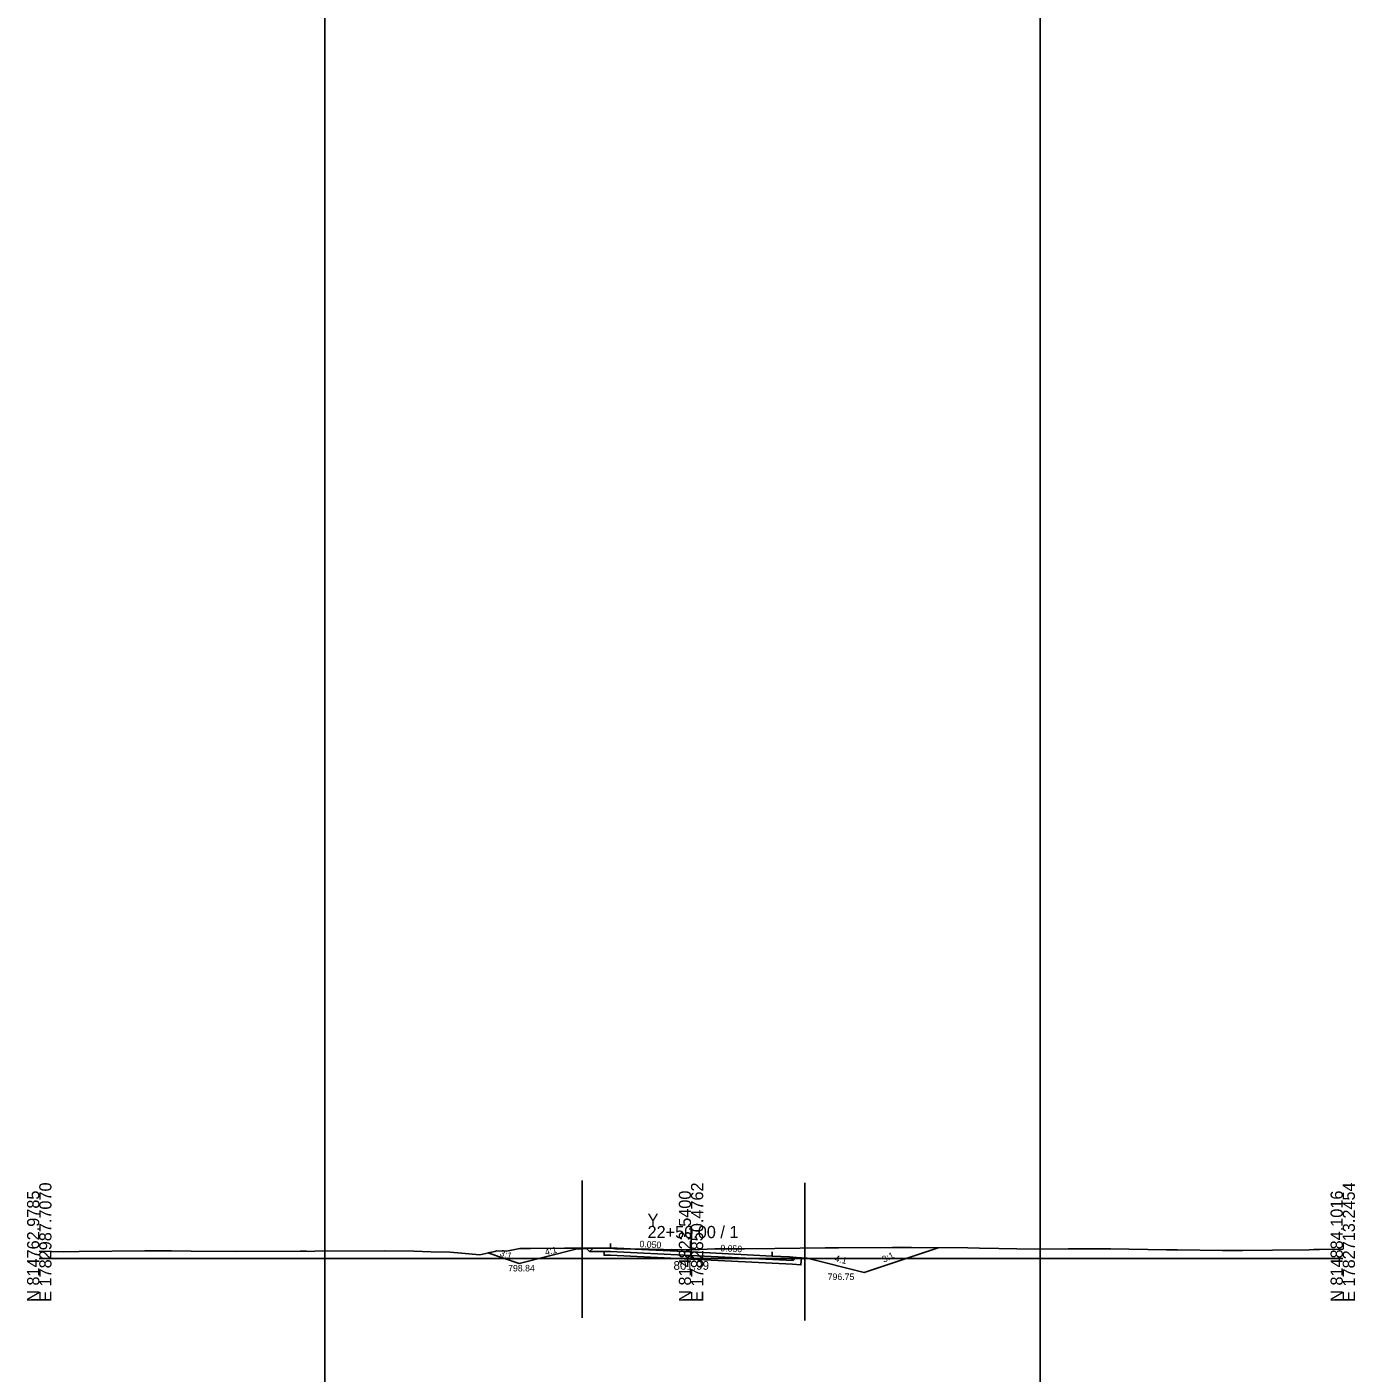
# Model space of a CAD drawing. Extents: x -12583 to 5303, y -44 to 25667.
# Drawn here: x 997.2 to 1302.8, y 2973.6 to 3283.5 of the extents above; entities that cross this region are included whole.
import ezdxf

# ---------------------------------------------------------------- set-up
doc = ezdxf.new("R2010")
doc.units = 0
for name, color, linetype in [('Exist Cross Section Cell', 7, 'Continuous'), ('Exist XS Center Line Elevation Label', 7, 'Continuous'), ('Exist XS Ground Line', 7, 'Continuous'), ('Prop CMT Shallow Undercut', 7, 'Continuous'), ('Prop XS Ditch Slope Text', 7, 'Continuous'), ('Prop XS Ditch Standard Text', 7, 'Continuous'), ('Prop XS Dump Level', 7, 'Continuous'), ('Prop XS Earthwork Shape', 7, 'Continuous'), ('Prop XS Earthwork Undercut', 7, 'Continuous'), ('Prop XS EOT Tick Mark', 7, 'Continuous'), ('Prop XS Exc Vertical Line 1', 7, 'Continuous'), ('Prop XS Exc Vertical Line 2', 7, 'Continuous'), ('Prop XS Finish Grade', 7, 'Continuous'), ('Prop XS Finish Grade Earthwork', 7, 'Continuous'), ('Prop XS Finish Grade Paved Shoulder', 7, 'Continuous'), ('Prop XS Finish Grade Pavement', 7, 'Continuous'), ('Prop XS Pvmt Edge Slope', 7, 'Continuous'), ('Prop XS SE Text', 7, 'Continuous'), ('Prop XS Side Slope Text', 7, 'Continuous'), ('Prop XS Subgrade Earthwork', 7, 'Continuous'), ('Scratch_Level_1', 7, 'Continuous'), ('Scratch_Level_2', 7, 'Continuous'), ('Scratch_Level_3', 7, 'Continuous')]:
    doc.layers.add(name, color=color, linetype=linetype)

msp = doc.modelspace()

# ---------------------------------------------------------------- linework, layer by layer
at = {"layer": 'Exist Cross Section Cell'}
for p, q in [((1150, 3000), (1150, 3007.47)), ((1000, 3000), (1150, 3000)), ((1150, 3000), (1300, 3000))]:
    msp.add_line(p, q, dxfattribs=at)
at = {"layer": 'Exist XS Ground Line'}
for p, q in [((1000, 3001.69), (1005.69, 3001.49)), ((1005.69, 3001.49), (1009.17, 3001.57)), ((1009.17, 3001.57), (1024.26, 3001.71)), ((1024.26, 3001.71), (1030.41, 3001.72)), ((1030.41, 3001.72), (1034.95, 3001.7)), ((1034.95, 3001.7), (1045.44, 3001.6)), ((1045.44, 3001.6), (1060.06, 3001.63)), ((1060.06, 3001.63), (1061.48, 3001.63)), ((1061.48, 3001.63), (1061.94, 3001.62)), ((1061.94, 3001.62), (1063.46, 3001.64)), ((1063.46, 3001.64), (1079.38, 3001.75)), ((1079.38, 3001.75), (1086.24, 3001.66)), ((1086.24, 3001.66), (1090.13, 3001.55)), ((1090.13, 3001.55), (1094.53, 3001.42)), ((1094.53, 3001.42), (1096.36, 3001.28)), ((1096.36, 3001.28), (1101.38, 3000.83)), ((1101.38, 3000.83), (1104.87, 3001.62)), ((1104.87, 3001.62), (1105.26, 3001.71)), ((1105.26, 3001.71), (1107.53, 3001.7)), ((1107.53, 3001.7), (1110.61, 3002.29)), ((1110.61, 3002.29), (1113.06, 3002.3)), ((1113.06, 3002.3), (1120.9, 3002.39)), ((1120.9, 3002.39), (1129.84, 3002.37)), ((1129.84, 3002.37), (1131.7, 3002.36)), ((1131.7, 3002.36), (1132.66, 3002.23)), ((1132.66, 3002.23), (1133.15, 3002.21)), ((1133.15, 3002.21), (1133.92, 3002.24)), ((1133.92, 3002.24), (1135.09, 3002.17)), ((1135.09, 3002.17), (1137.78, 3002.12)), ((1137.78, 3002.12), (1140.38, 3002.14)), ((1140.38, 3002.14), (1143.66, 3002.03)), ((1143.66, 3002.03), (1144.89, 3001.99)), ((1144.89, 3001.99), (1145.48, 3002.04)), ((1145.48, 3002.04), (1150.18, 3001.99)), ((1150.18, 3001.99), (1155.46, 3002.17)), ((1155.46, 3002.17), (1162.29, 3002.23)), ((1162.29, 3002.23), (1169.28, 3002.28)), ((1169.28, 3002.28), (1180.9, 3002.42)), ((1180.9, 3002.42), (1183.92, 3002.47)), ((1183.92, 3002.47), (1196.41, 3002.48)), ((1196.41, 3002.48), (1198.41, 3002.49)), ((1198.41, 3002.49), (1198.91, 3002.49)), ((1198.91, 3002.49), (1200.72, 3002.48)), ((1200.72, 3002.48), (1213.68, 3002.4)), ((1213.68, 3002.4), (1216.39, 3002.37)), ((1216.39, 3002.37), (1220.87, 3002.27)), ((1220.87, 3002.27), (1229.11, 3002.15)), ((1229.11, 3002.15), (1236.78, 3002.21)), ((1236.78, 3002.21), (1246.56, 3002.18)), ((1246.56, 3002.18), (1259.41, 3002)), ((1259.41, 3002), (1261.95, 3001.96)), ((1261.95, 3001.96), (1272.3, 3001.83)), ((1272.3, 3001.83), (1276.91, 3001.82)), ((1276.91, 3001.82), (1283.87, 3001.91)), ((1283.87, 3001.91), (1292.28, 3002.01)), ((1292.28, 3002.01), (1293.38, 3002.02)), ((1293.38, 3002.02), (1294.67, 3002.05)), ((1294.67, 3002.05), (1300, 3002.12))]:
    msp.add_line(p, q, dxfattribs=at)
at = {"layer": 'Prop CMT Shallow Undercut'}
msp.add_lwpolyline([(1130, 3001.61), (1130, 3000.73), (1131.45, 3000.74), (1149.95, 2999.82), (1168.65, 2998.88), (1173.33, 2998.65), (1175.31, 2998.49), (1175.44, 3000.13), (1174.24, 3000.23), (1173.53, 2999.52), (1149.96, 3000.69), (1131.45, 3001.62)], close=True, dxfattribs=at)
at = {"layer": 'Prop XS Dump Level'}
for p, q in [((1131.47, 3002.41), (1150, 3001.48)), ((1150, 3001.48), (1168.7, 3000.55))]:
    msp.add_line(p, q, dxfattribs=at)
at = {"layer": 'Prop XS Earthwork Shape'}
msp.add_lwpolyline([(1131.45, 3001.62), (1126.67, 3001.57), (1125.97, 3002.27), (1123.47, 3002.09), (1110.46, 2998.84), (1103.24, 3001.25), (1104.87, 3001.62), (1105.26, 3001.71), (1107.53, 3001.7), (1110.61, 3002.29), (1113.06, 3002.3), (1120.9, 3002.39), (1129.84, 3002.37), (1131.7, 3002.36), (1132.66, 3002.23), (1133.15, 3002.21), (1133.92, 3002.24), (1135.09, 3002.17), (1137.78, 3002.12), (1140.38, 3002.14), (1143.66, 3002.03), (1144.89, 3001.99), (1145.48, 3002.04), (1150.18, 3001.99), (1155.46, 3002.17), (1162.29, 3002.23), (1169.28, 3002.28), (1180.9, 3002.42), (1183.92, 3002.47), (1196.41, 3002.48), (1198.41, 3002.49), (1198.91, 3002.49), (1200.72, 3002.48), (1206.89, 3002.44), (1189.82, 2996.75), (1176.7, 3000.03), (1174.24, 3000.23), (1173.53, 2999.52), (1149.96, 3000.69)], close=True, dxfattribs=at)
at = {"layer": 'Prop XS Earthwork Undercut'}
for p, q in [((1131.45, 3001.62), (1130, 3001.61)), ((1130, 3001.61), (1130, 3000.73)), ((1130, 3000.73), (1131.45, 3000.74)), ((1149.96, 3000.69), (1131.45, 3001.62)), ((1131.45, 3000.74), (1149.95, 2999.82)), ((1149.95, 2999.82), (1168.65, 2998.88)), ((1173.53, 2999.52), (1149.96, 3000.69)), ((1174.24, 3000.23), (1173.53, 2999.52)), ((1175.31, 2998.49), (1175.44, 3000.13)), ((1168.65, 2998.88), (1173.33, 2998.65)), ((1173.33, 2998.65), (1175.31, 2998.49))]:
    msp.add_line(p, q, dxfattribs=at)
at = {"layer": 'Prop XS EOT Tick Mark'}
for p, q in [((1131.47, 3002.41), (1131.47, 3003.41)), ((1168.7, 3000.55), (1168.7, 3001.55))]:
    msp.add_line(p, q, dxfattribs=at)
at = {"layer": 'Prop XS Exc Vertical Line 1'}
msp.add_line((1124.93, 2986.3), (1124.93, 3017.96), dxfattribs=at)
at = {"layer": 'Prop XS Exc Vertical Line 2'}
msp.add_line((1176.18, 2985.73), (1176.18, 3017.39), dxfattribs=at)
at = {"layer": 'Prop XS Finish Grade'}
for p, q in [((1127.47, 3002.37), (1125.97, 3002.27)), ((1172.7, 3000.35), (1174.24, 3000.23))]:
    msp.add_line(p, q, dxfattribs=at)
at = {"layer": 'Prop XS Finish Grade Earthwork'}
for p, q in [((1110.46, 2998.84), (1103.24, 3001.25)), ((1123.47, 3002.09), (1110.46, 2998.84)), ((1123.47, 3002.09), (1125.97, 3002.27)), ((1174.24, 3000.23), (1176.7, 3000.03)), ((1176.7, 3000.03), (1189.82, 2996.75)), ((1189.82, 2996.75), (1206.89, 3002.44))]:
    msp.add_line(p, q, dxfattribs=at)
at = {"layer": 'Prop XS Finish Grade Paved Shoulder'}
for p, q in [((1131.47, 3002.41), (1127.47, 3002.37)), ((1168.7, 3000.55), (1172.7, 3000.35))]:
    msp.add_line(p, q, dxfattribs=at)
at = {"layer": 'Prop XS Finish Grade Pavement'}
for p, q in [((1131.47, 3002.41), (1150, 3001.48)), ((1150, 3001.48), (1168.7, 3000.55))]:
    msp.add_line(p, q, dxfattribs=at)
at = {"layer": 'Prop XS Pvmt Edge Slope'}
for p, q in [((1127.47, 3002.37), (1126.67, 3001.57)), ((1172.7, 3000.35), (1173.53, 2999.52))]:
    msp.add_line(p, q, dxfattribs=at)
at = {"layer": 'Prop XS Subgrade Earthwork'}
for p, q in [((1126.67, 3001.57), (1125.97, 3002.27)), ((1131.45, 3001.62), (1126.67, 3001.57)), ((1131.45, 3001.62), (1149.96, 3000.69)), ((1149.96, 3000.69), (1173.53, 2999.52)), ((1173.53, 2999.52), (1174.24, 3000.23))]:
    msp.add_line(p, q, dxfattribs=at)
at = {"layer": 'Scratch_Level_1'}
msp.add_line((1065.76, 8031.12), (1065.76, -44.39), dxfattribs=at)
at = {"layer": 'Scratch_Level_2'}
msp.add_line((1230.36, 8031.12), (1230.36, -44.39), dxfattribs=at)
at = {"layer": 'Scratch_Level_3'}
msp.add_lwpolyline([(1137.04, 3002.13), (1150, 3001.48), (1168.7, 3000.55), (1172.7, 3000.35), (1174.24, 3000.23), (1173.53, 2999.52), (1149.96, 3000.69), (1131.45, 3001.62), (1126.67, 3001.57), (1125.97, 3002.27), (1127.47, 3002.37), (1129.84, 3002.37), (1131.7, 3002.36), (1132.66, 3002.23), (1133.15, 3002.21), (1133.92, 3002.24), (1135.09, 3002.17)], close=True, dxfattribs=at)

# ---------------------------------------------------------------- texts
at = {"layer": 'Exist Cross Section Cell'}
for s, p in [('N 814762.9785', (1000, 2990)), ('E 1782987.7070', (1002.8, 2990)), ('N 814823.5400', (1150, 2990)), ('E 1782850.4762', (1152.8, 2990)), ('N 814884.1016', (1300, 2990)), ('E 1782713.2454', (1302.8, 2990))]:
    msp.add_text(s, height=2.8, rotation=90, dxfattribs=at).set_placement(p)
for s, p in [('Y', (1140, 3007.47)), ('22+50.00 / 1', (1140, 3004.67))]:
    msp.add_text(s, height=2.8, dxfattribs=at).set_placement(p)
at = {"layer": 'Exist XS Center Line Elevation Label'}
msp.add_text('801.99', height=2, dxfattribs=at).set_placement((1145.97, 2997.38))
at = {"layer": 'Prop XS Ditch Slope Text'}
for rotation, p in [(14.0362, (1116.57, 3000.65)), (345.9638, (1182.96, 2999.35))]:
    msp.add_text('4:1', height=1.5, rotation=rotation, dxfattribs=at).set_placement(p)
at = {"layer": 'Prop XS Ditch Standard Text'}
for s, p in [('798.84', (1107.91, 2997)), ('796.75', (1181.46, 2995.03))]:
    msp.add_text(s, height=1.5, dxfattribs=at).set_placement(p)
at = {"layer": 'Prop XS Dump Level'}
for p in [(1123.47, 3002.05), (1176.7, 2999.99)]:
    msp.add_text('Case2', height=0.04, dxfattribs=at).set_placement(p)
at = {"layer": 'Prop XS SE Text'}
for p in [(1138.11, 3002.58), (1156.73, 3001.65)]:
    msp.add_text('0.050', height=1.5, rotation=357.1376, dxfattribs=at).set_placement(p)
at = {"layer": 'Prop XS Side Slope Text'}
for rotation, p in [(341.5651, (1105.86, 3000.65)), (26.5651, (1194.41, 2998.98))]:
    msp.add_text('3:1', height=1.5, rotation=rotation, dxfattribs=at).set_placement(p)

doc.saveas('drawing.dxf')
